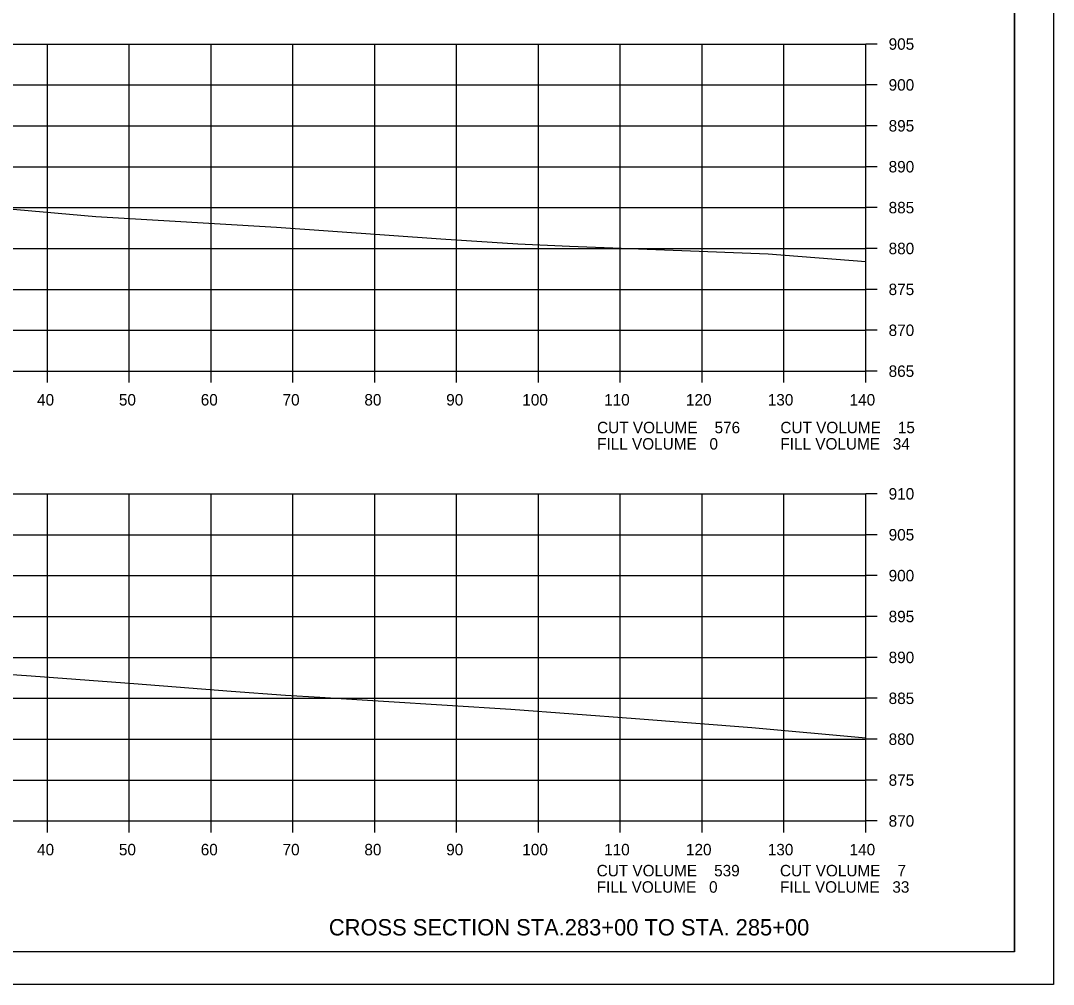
# Model space of a CAD drawing. Extents: x 1486524 to 1499135, y 326561 to 337924.
# Drawn here: x 1489019.6 to 1489145.8, y 332139.3 to 332257.1 of the extents above; entities that cross this region are included whole.
import ezdxf

# ---------------------------------------------------------------- set-up
doc = ezdxf.new("R2010")
doc.units = 0
for name, color, linetype in [('E_Const Align', 7, 'Continuous'), ('E_Const Align Station', 7, 'Continuous'), ('E_Ownership Information', 7, 'Continuous'), ('E_Property Line', 7, 'Continuous'), ('E_Proposed ROW Fig Annot', 7, 'Continuous'), ('E_Quarter Calls', 7, 'Continuous'), ('E_Tract Number', 7, 'Continuous')]:
    doc.layers.add(name, color=color, linetype=linetype)

msp = doc.modelspace()

# ---------------------------------------------------------------- linework, layer by layer
at = {"layer": 'E_Const Align'}
for p, q in [((1489122.89, 332214.27), (1489122.89, 332254.27)), ((1489124.29, 332254.27), (1489122.89, 332254.27)), ((1489124.29, 332249.27), (1489122.89, 332249.27)), ((1489124.29, 332244.27), (1489122.89, 332244.27)), ((1489124.29, 332239.27), (1489122.89, 332239.27)), ((1489124.29, 332234.27), (1489122.89, 332234.27)), ((1489124.29, 332229.27), (1489122.89, 332229.27)), ((1489124.29, 332224.27), (1489122.89, 332224.27)), ((1489124.29, 332219.27), (1489122.89, 332219.27)), ((1488842.89, 332214.27), (1489122.89, 332214.27)), ((1489022.89, 332212.87), (1489022.89, 332214.27)), ((1489032.89, 332212.87), (1489032.89, 332214.27)), ((1489042.89, 332212.87), (1489042.89, 332214.27)), ((1489052.89, 332212.87), (1489052.89, 332214.27)), ((1489062.89, 332212.87), (1489062.89, 332214.27)), ((1489072.89, 332212.87), (1489072.89, 332214.27)), ((1489082.89, 332212.87), (1489082.89, 332214.27)), ((1489092.89, 332212.87), (1489092.89, 332214.27)), ((1489102.89, 332212.87), (1489102.89, 332214.27)), ((1489112.89, 332212.87), (1489112.89, 332214.27)), ((1489122.89, 332212.87), (1489122.89, 332214.27)), ((1489124.29, 332214.27), (1489122.89, 332214.27)), ((1489122.89, 332159.27), (1489122.89, 332199.27)), ((1489124.29, 332199.27), (1489122.89, 332199.27)), ((1489124.29, 332194.27), (1489122.89, 332194.27)), ((1489124.29, 332189.27), (1489122.89, 332189.27)), ((1489124.29, 332184.27), (1489122.89, 332184.27)), ((1489124.29, 332179.27), (1489122.89, 332179.27)), ((1489124.29, 332174.27), (1489122.89, 332174.27)), ((1489124.29, 332169.27), (1489122.89, 332169.27)), ((1489124.29, 332164.27), (1489122.89, 332164.27)), ((1488842.89, 332159.27), (1489122.89, 332159.27)), ((1489022.89, 332157.87), (1489022.89, 332159.27)), ((1489032.89, 332157.87), (1489032.89, 332159.27)), ((1489042.89, 332157.87), (1489042.89, 332159.27)), ((1489052.89, 332157.87), (1489052.89, 332159.27)), ((1489062.89, 332157.87), (1489062.89, 332159.27)), ((1489072.89, 332157.87), (1489072.89, 332159.27)), ((1489082.89, 332157.87), (1489082.89, 332159.27)), ((1489092.89, 332157.87), (1489092.89, 332159.27)), ((1489102.89, 332157.87), (1489102.89, 332159.27)), ((1489112.89, 332157.87), (1489112.89, 332159.27)), ((1489122.89, 332157.87), (1489122.89, 332159.27)), ((1489124.29, 332159.27), (1489122.89, 332159.27))]:
    msp.add_line(p, q, dxfattribs=at)
at = {"layer": 'E_Ownership Information'}
for p, q in [((1488842.89, 332254.27), (1489122.89, 332254.27)), ((1489022.89, 332214.27), (1489022.89, 332254.27)), ((1489032.89, 332214.27), (1489032.89, 332254.27)), ((1489042.89, 332214.27), (1489042.89, 332254.27)), ((1489052.89, 332214.27), (1489052.89, 332254.27)), ((1489062.89, 332214.27), (1489062.89, 332254.27)), ((1489072.89, 332214.27), (1489072.89, 332254.27)), ((1489082.89, 332214.27), (1489082.89, 332254.27)), ((1489092.89, 332214.27), (1489092.89, 332254.27)), ((1489102.89, 332214.27), (1489102.89, 332254.27)), ((1489112.89, 332214.27), (1489112.89, 332254.27)), ((1489122.89, 332214.27), (1489122.89, 332254.27)), ((1488842.89, 332249.27), (1489122.89, 332249.27)), ((1488842.89, 332244.27), (1489122.89, 332244.27)), ((1488842.89, 332239.27), (1489122.89, 332239.27)), ((1488842.89, 332234.27), (1489122.89, 332234.27)), ((1488842.89, 332229.27), (1489122.89, 332229.27)), ((1488842.89, 332224.27), (1489122.89, 332224.27)), ((1488842.89, 332219.27), (1489122.89, 332219.27)), ((1488842.89, 332214.27), (1489122.89, 332214.27)), ((1488842.89, 332199.27), (1489122.89, 332199.27)), ((1489022.89, 332159.27), (1489022.89, 332199.27)), ((1489032.89, 332159.27), (1489032.89, 332199.27)), ((1489042.89, 332159.27), (1489042.89, 332199.27)), ((1489052.89, 332159.27), (1489052.89, 332199.27)), ((1489062.89, 332159.27), (1489062.89, 332199.27)), ((1489072.89, 332159.27), (1489072.89, 332199.27)), ((1489082.89, 332159.27), (1489082.89, 332199.27)), ((1489092.89, 332159.27), (1489092.89, 332199.27)), ((1489102.89, 332159.27), (1489102.89, 332199.27)), ((1489112.89, 332159.27), (1489112.89, 332199.27)), ((1489122.89, 332159.27), (1489122.89, 332199.27)), ((1488842.89, 332194.27), (1489122.89, 332194.27)), ((1488842.89, 332189.27), (1489122.89, 332189.27)), ((1488842.89, 332184.27), (1489122.89, 332184.27)), ((1488842.89, 332179.27), (1489122.89, 332179.27)), ((1488842.89, 332174.27), (1489122.89, 332174.27)), ((1488842.89, 332169.27), (1489122.89, 332169.27)), ((1488842.89, 332164.27), (1489122.89, 332164.27)), ((1488842.89, 332159.27), (1489122.89, 332159.27))]:
    msp.add_line(p, q, dxfattribs=at)
at = {"layer": 'E_Property Line'}
for q in [(1489141.07, 332348.73), (1488824.89, 332143.27)]:
    msp.add_line((1489141.07, 332143.27), q, dxfattribs=at)
at = {"layer": 'E_Quarter Calls'}
msp.add_line((1488812.48, 332139.3), (1489145.82, 332139.3), dxfattribs=at)
for points in [[(1488812.48, 332352.63), (1489145.82, 332352.63), (1489145.82, 332139.29), (1488812.48, 332139.29)], [(1489058.81, 332348.73), (1489058.81, 332338.85), (1489094.54, 332338.85), (1489094.54, 332335.93), (1489117.74, 332335.93), (1489117.74, 332311.6), (1489141.07, 332311.6), (1489141.07, 332143.27), (1488824.89, 332143.27), (1488824.89, 332348.73)]]:
    msp.add_lwpolyline(points, close=True, dxfattribs=at)
at = {"layer": 'E_Tract Number'}
for points in [[(1489015.9, 332234.31), (1489028.82, 332233.2), (1489030.2, 332233.11), (1489036.43, 332232.72), (1489050.89, 332231.86), (1489070.96, 332230.45), (1489080.38, 332229.85), (1489086.7, 332229.57), (1489110.97, 332228.62), (1489122.89, 332227.67)], [(1489014.45, 332177.45), (1489020.89, 332177), (1489033.45, 332176.08), (1489045.33, 332175.16), (1489051.96, 332174.65), (1489056.16, 332174.4), (1489079.51, 332172.93), (1489094.75, 332171.78), (1489108.95, 332170.71), (1489122.89, 332169.45)]]:
    msp.add_lwpolyline(points, dxfattribs=at)

# ---------------------------------------------------------------- texts
at = {"layer": 'E_Const Align Station'}
for s, p in [('905', (1489125.69, 332253.57)), ('900', (1489125.69, 332248.57)), ('895', (1489125.69, 332243.57)), ('890', (1489125.69, 332238.57)), ('885', (1489125.69, 332233.57)), ('880', (1489125.69, 332228.57)), ('875', (1489125.69, 332223.57)), ('870', (1489125.69, 332218.57)), ('865', (1489125.69, 332213.57)), ('40', (1489021.62, 332210.07)), ('50', (1489031.62, 332210.07)), ('60', (1489041.62, 332210.07)), ('70', (1489051.62, 332210.07)), ('80', (1489061.62, 332210.07)), ('90', (1489071.62, 332210.07)), ('100', (1489080.92, 332210.07)), ('110', (1489090.92, 332210.07)), ('120', (1489100.92, 332210.07)), ('130', (1489110.92, 332210.07)), ('140', (1489120.92, 332210.07)), ('CUT VOLUME    576', (1489090.06, 332206.68)), ('CUT VOLUME    15', (1489112.46, 332206.68)), ('FILL VOLUME   0', (1489090.06, 332204.68)), ('FILL VOLUME   34', (1489112.46, 332204.68)), ('910', (1489125.69, 332198.57)), ('905', (1489125.69, 332193.57)), ('900', (1489125.69, 332188.57)), ('895', (1489125.69, 332183.57)), ('890', (1489125.69, 332178.57)), ('885', (1489125.69, 332173.57)), ('880', (1489125.69, 332168.57)), ('875', (1489125.69, 332163.57)), ('870', (1489125.69, 332158.57)), ('40', (1489021.62, 332155.07)), ('50', (1489031.62, 332155.07)), ('60', (1489041.62, 332155.07)), ('70', (1489051.62, 332155.07)), ('80', (1489061.62, 332155.07)), ('90', (1489071.62, 332155.07)), ('100', (1489080.92, 332155.07)), ('110', (1489090.92, 332155.07)), ('120', (1489100.92, 332155.07)), ('130', (1489110.92, 332155.07)), ('140', (1489120.92, 332155.07)), ('CUT VOLUME    539', (1489090.01, 332152.5)), ('CUT VOLUME    7', (1489112.41, 332152.5)), ('FILL VOLUME   0', (1489090.01, 332150.5)), ('FILL VOLUME   33', (1489112.41, 332150.5))]:
    msp.add_text(s, height=1.4, dxfattribs=at).set_placement(p)
at = {"layer": 'E_Proposed ROW Fig Annot'}
msp.add_text('CROSS SECTION STA.283+00 TO STA. 285+00', height=2, dxfattribs=at).set_placement((1489057.28, 332145.27))

doc.saveas('drawing.dxf')
